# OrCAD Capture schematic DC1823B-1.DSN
size A
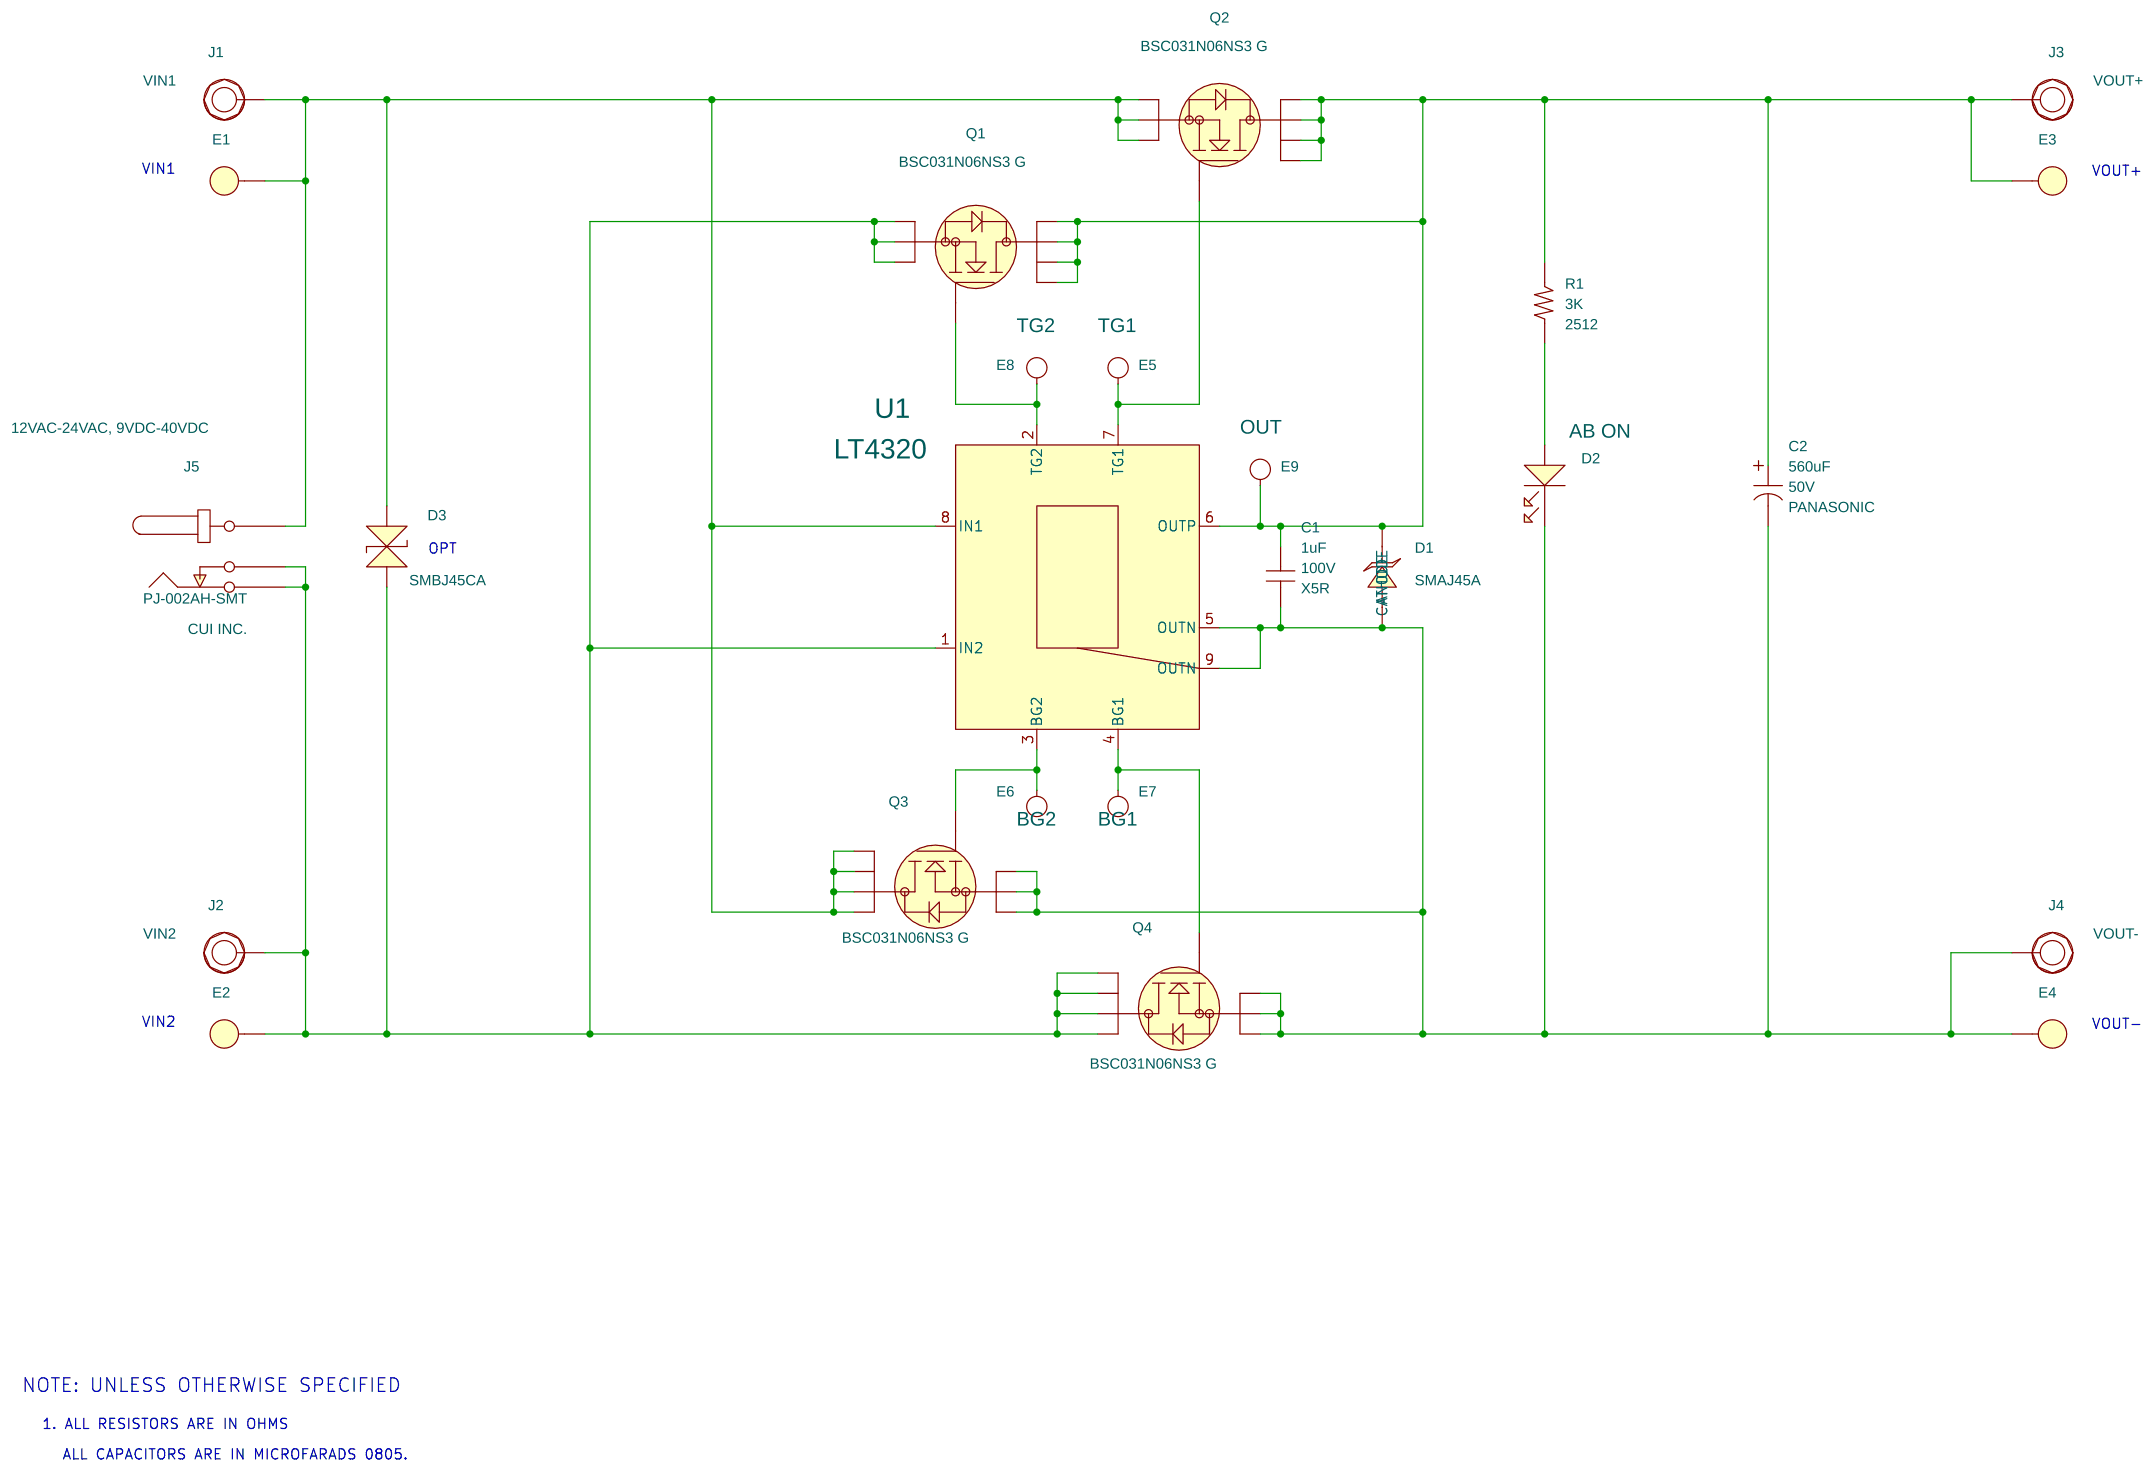
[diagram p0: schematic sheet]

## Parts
C1  1uF  [0805]
C2  560uF  [C-SANYO-12.5X25]
D1  SMAJ45A  [SMA-DIODE]
D2  SML-012P8T  [LED-ROHM-SML-01]
D3  SMBJ45CA  [SMB-DIODE]
E1  PAD150-094  [MILL-MAX-2501-2]
E2  PAD150-094  [MILL-MAX-2501-2]
E3  PAD150-094  [MILL-MAX-2501-2]
E4  PAD150-094  [MILL-MAX-2501-2]
E5  TG1  [SMTP]
E6  BG2  [SMTP]
E7  BG1  [SMTP]
E8  TG2  [SMTP]
E9  OUT  [SMTP]
J1  Banana Jack  [KEYSTONE-575-4]
J2  Banana Jack  [KEYSTONE-575-4]
J3  Banana Jack  [KEYSTONE-575-4]
J4  Banana Jack  [KEYSTONE-575-4]
J5  PJ-002AH  [CON-CUI-PJ002AH-SMT]
Q1  BSC031N06NS3 G  [SO8-POWERPAK]
Q2  BSC031N06NS3 G  [SO8-POWERPAK]
Q3  BSC031N06NS3 G  [SO8-POWERPAK]
Q4  BSC031N06NS3 G  [SO8-POWERPAK]
R1  3K  [2512]
U1  LT4320  [DFN8DD]

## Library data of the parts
C1 = CAP-NP: Tempco: X5R; Voltage Rating: 100V
C2 = CAP: Part #: PANASONIC; Voltage Rating: 50V
D1 = DIODE_TVS_3
D2 = LED-ROHM-SML-012P8TT86-GREEN: 1ST PART FIELD: AB ON
D3 = SMBJ15CA
E1 = E: 10th Part Field: 9V - 40V; 9th Part Field: VIN1
E2 = E: 10th Part Field: 12VAC-24VAC, 9VDC-40VDC; 9th Part Field: VIN2
E3 = E: 10th Part Field: XV / XA; 9th Part Field: VOUT+
E4 = E: 10th Part Field: XV / XA; 9th Part Field: VOUT-
E5-E9 = E-100SMT
J1-J4 = E-KEY-575
J5 = PJ-002AH(CUI_INC): 4th Part Field: CUI INC.; 5th Part Field: PJ-002AH-SMT
Q1-Q4 = FDMS86500L_0
R1 = R
U1 = LT4320IMSE-MSE12_5

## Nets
N17472004: D3.1 E1.1(A) J1.1 J5.1 Q2.1 Q2.2 Q2.3 Q3.5 Q3.6 Q3.7 Q3.8 U1.8(IN1)
N17472016: D3.2 E2.1(A) J2.1 J5.2 J5.3 Q1.1 Q1.2 Q1.3 Q4.5 Q4.6 Q4.7 Q4.8 U1.1(IN2)
N17472090: C1.1 C2.1 D1.1(CATHODE) E3.1(A) E9.1(A) J3.1 Q1.5 Q1.6 Q1.7 Q1.8 Q2.5 Q2.6 Q2.7 Q2.8 R1.1 U1.6(OUTP)
N17472092: C1.2 C2.2 D1.2(ANODE) D2.2 E4.1(A) J4.1 Q3.1 Q3.2 Q3.3 Q4.1 Q4.2 Q4.3 U1.5(OUTN) U1.9(OUTN)
N17472134: D2.1 R1.2
N17593568: E5.1(A) Q2.4 U1.7(TG1)
N17593689: E8.1(A) Q1.4 U1.2(TG2)
N17595695: E6.1(A) Q3.4 U1.3(BG2)
N17596091: E7.1(A) Q4.4 U1.4(BG1)

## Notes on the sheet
- VIN1
- VOUT+
- OPT
- VIN2
- VOUT-
- NOTE: UNLESS OTHERWISE SPECIFIED
- 1. ALL RESISTORS ARE IN OHMS
- ALL CAPACITORS ARE IN MICROFARADS 0805.
